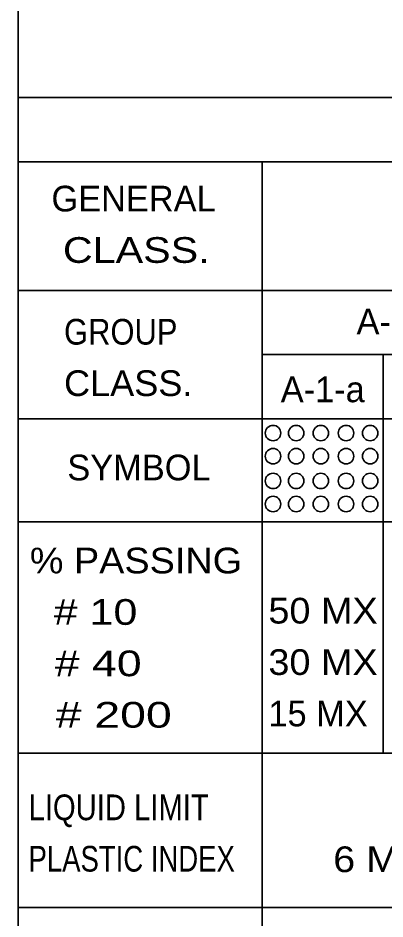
# Model space of a CAD drawing. Extents: x 2137492.6 to 2137529.1, y 2137475.8 to 2137563.
# Drawn here: x 2137493.171 to 2137494.599, y 2137553.178 to 2137556.682 of the extents above; entities that cross this region are included whole.
import ezdxf
from ezdxf.enums import TextEntityAlignment as Align

# ---------------------------------------------------------------- set-up
doc = ezdxf.new("R2010")
doc.units = 0
doc.header["$LTSCALE"] = 0.04
doc.layers.add('1', color=7, linetype='Continuous', lineweight=35)

msp = doc.modelspace()

# ---------------------------------------------------------------- linework, layer by layer
at = {"layer": '1'}
for p, q in [((2137493.171, 2137556.373), (2137501.871, 2137556.373)), ((2137493.171, 2137556.123), (2137501.871, 2137556.123)), ((2137494.121, 2137556.123), (2137494.121, 2137551.631)), ((2137493.171, 2137555.623), (2137501.871, 2137555.623)), ((2137494.121, 2137555.373), (2137499.271, 2137555.373)), ((2137494.591, 2137553.823), (2137494.591, 2137555.374)), ((2137493.171, 2137555.123), (2137501.871, 2137555.123)), ((2137493.171, 2137554.723), (2137501.871, 2137554.723)), ((2137493.171, 2137553.823), (2137501.871, 2137553.823)), ((2137493.171, 2137553.223), (2137499.271, 2137553.223))]:
    msp.add_line(p, q, dxfattribs=at)
msp.add_lwpolyline([(2137493.171, 2137561.718), (2137493.171, 2137539.727), (2137528.371, 2137539.727)], dxfattribs=at)
for centre in [(2137494.16306, 2137555.06786), (2137494.25306, 2137555.06786), (2137494.34906, 2137555.06786), (2137494.44706, 2137555.06786), (2137494.54106, 2137555.06786), (2137494.16306, 2137554.97786), (2137494.25306, 2137554.97786), (2137494.34906, 2137554.97786), (2137494.44706, 2137554.97786), (2137494.54106, 2137554.97786), (2137494.16306, 2137554.88186), (2137494.25306, 2137554.88186), (2137494.34906, 2137554.88186), (2137494.44706, 2137554.88186), (2137494.54106, 2137554.88186), (2137494.16306, 2137554.79186), (2137494.25306, 2137554.79186), (2137494.34906, 2137554.79186), (2137494.44706, 2137554.79186), (2137494.54106, 2137554.79186)]:
    msp.add_circle(centre, 0.03, dxfattribs=at)

# ---------------------------------------------------------------- texts
for s, p in [('GENERAL', (2137493.301, 2137555.93)), ('15 MX', (2137494.145, 2137553.927))]:
    msp.add_text(s, height=0.1, dxfattribs=at).set_placement(p)
for s, width, p in [(' CLASS.', 1.2, (2137493.301, 2137555.73)), ('GROUP', 0.9, (2137493.35, 2137555.412)), ('CLASS.', 1.05, (2137493.35, 2137555.212)), ('% PASSING', 1.1, (2137493.217, 2137554.522)), ('  # 10', 1.25, (2137493.217, 2137554.322)), ('50 MX', 1.1, (2137494.145, 2137554.327)), ('  # 40', 1.3, (2137493.217, 2137554.122)), ('30 MX', 1.1, (2137494.145, 2137554.127)), ('  # 200', 1.35, (2137493.217, 2137553.922)), ('LIQUID LIMIT', 0.85, (2137493.212, 2137553.562)), ('PLASTIC INDEX', 0.8, (2137493.212, 2137553.362))]:
    msp.add_text(s, height=0.1, dxfattribs=dict(at, width=width)).set_placement(p)
for s, p in [('A-1', (2137494.592, 2137555.452)), ('A-1-a', (2137494.3565, 2137555.188)), ('SYMBOL', (2137493.6415, 2137554.884))]:
    msp.add_text(s, height=0.1, dxfattribs=at).set_placement(p, align=Align.CENTER)
at = {"layer": '1', "width": 1.15}
msp.add_text('6 MX', height=0.1, dxfattribs=at).set_placement((2137494.5765, 2137553.36), align=Align.CENTER)

doc.saveas('drawing.dxf')
